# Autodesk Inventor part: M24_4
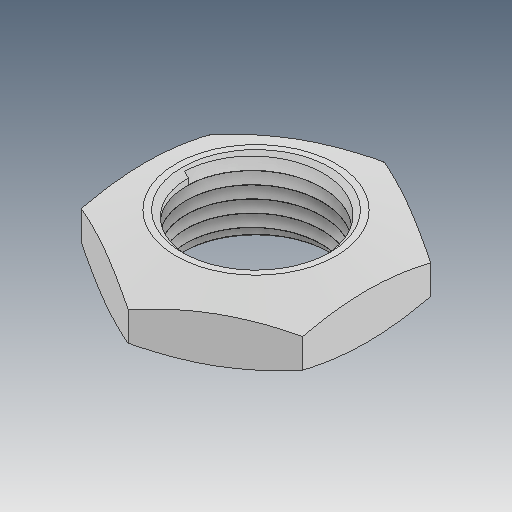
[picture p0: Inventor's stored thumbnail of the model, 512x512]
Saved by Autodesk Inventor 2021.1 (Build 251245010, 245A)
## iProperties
Created: 2019-05
Part Number: M24_4
Material: Ogólny
Document SubType Name: Modeling
Designer: user
Density: 1 g/cm^3
Appearance: Domyślna
Author: user
Revision Number: ÈÎºÎ
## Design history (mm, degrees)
feature "ÊäÈë1"
node "Bryła1"
